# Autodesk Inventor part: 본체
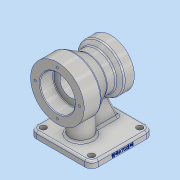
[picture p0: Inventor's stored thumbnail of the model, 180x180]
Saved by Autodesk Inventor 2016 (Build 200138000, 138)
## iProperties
Created: 2019-01
Part Number: 본체
Material: 알루미늄 6061
Document SubType Name: Modeling
Designer: 3sil_cad018
Density: 2.7 g/cm^3
Appearance: 알루미늄 - 평지
Author: 3sil_cad018
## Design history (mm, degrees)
sketch "스케치1"
  geometry: L1 (-51, 0)-(29, 0); L2 (-51, 0)-(-51, 40); L3 (-51, 40)-(-26, 40); L4 (-26, 40)-(-5.215, 28); L5 (-5.215, 28)-(8.126, 28); L6 (8.126, 28)-(14, 35); L7 (14, 35)-(29, 35); L8 (29, 35)-(29, 0); 2 further points
  constraints: 16 end point, 2 parallel, 2 vertical, 1 horizontal, 1 midpoint, 1 perpendicular, 1 point on line
  dimensions: "d0" = 80 distance of L1.start L1.end; "d1" = 80 diameter of L3 L1; "d2" = 25 distance of L2.end L3.end; "d3" = 15 distance of L6.end L7.end; "d4" = 70 diameter of L7 L1; "d5" = 30 deg angle of L4 L5; "d6" = 50 deg angle of L6 L5; "d7" = 51 distance from line of point (0, 0) L2; "d8" = 56 diameter of L5 L1
revolve "회전1" sketch "스케치1" stored, may be unused: angle "d9" = 90 deg
node "작업 평면1"
sketch "스케치2"
  geometry: L1 (46, 46)-(-46, 46); L2 (-46, 46)-(-46, -46); L3 (-46, -46)-(46, -46); L4 (46, -46)-(46, 46); L5 (46, 46)-(-46, -46); L6 (-46, 46)-(46, -46); 1 further point
  constraints: 12 end point, 2 midpoint, 2 parallel, 1 horizontal, 1 perpendicular
  dimensions: "d11" = 92 distance of L3.end L2.end; "d12" = 92 distance of L2.end L1.end
extrude "돌출1" join sketch "스케치2" distance "d13" = 10; taper "d14" = 0 deg
sketch "스케치3"
  geometry: L1 (-70.4, 0)-(65.4, 0) reference; L2 (-46, 46)-(-46, -46) reference; C1 r 16 at (-16, 0); 1 further point
  constraints: 1 centre point, 1 point on line
  dimensions: "d15" = 32 diameter of C1; "d16" = 30 distance from line of C1.centre L2
extrude "돌출2" join sketch "스케치3" stored distance "d17" = 10; taper "d18" = 0 deg
sketch "스케치4"
  geometry: L1 (0, -70)-(0, -28) reference; L2 (46, -70)-(-46, -70) reference; L3 (14, -35)-(29, -35) reference; L4 (36, -70)-(19.679, -35); L5 (46, -80)-(46, -70) reference; 1 further point
  constraints: 2 end point, 2 point on line
  dimensions: "d19" = 10 distance from line of L5 L4.start; "d20" = 25 deg angle of L4 L5
feature "리브1" sketch "스케치4" dims "d21" = 1, "d22" = 10, "d23" = 0, "d24" = 0, "d25" = 1, "d26" = 1
fillet "모깎기1" dims "d27" = 10
hole "구멍1" diameter "d30" = 9; stored, may be unused: countersink angle "d34" = 90 deg, drill point angle "d36" = 118 deg; dims "d28" = 10, "d29" = 10, "d31" = 6, "d32" = 4, "d33" = 2, "d35" = 8
hole "구멍2" diameter "d39" = 9; stored, may be unused: countersink angle "d43" = 90 deg, drill point angle "d45" = 118 deg; dims "d37" = 10, "d38" = 10, "d40" = 6, "d41" = 4, "d42" = 2, "d44" = 8
hole "구멍3" diameter "d48" = 9; stored, may be unused: countersink angle "d52" = 90 deg, drill point angle "d54" = 118 deg; dims "d46" = 10, "d47" = 10, "d49" = 6, "d50" = 4, "d51" = 2, "d53" = 8
hole "구멍4" diameter "d57" = 9; stored, may be unused: countersink angle "d61" = 90 deg, drill point angle "d63" = 118 deg; dims "d55" = 10, "d56" = 10, "d58" = 6, "d59" = 4, "d60" = 2, "d62" = 8
sketch "스케치5"
  geometry: C1 r 26 at (0, 0); 1 further point
  constraints: 1 centre point, 1 coincident
  dimensions: "d64" = 52 diameter of C1
extrude "돌출3" cut sketch "스케치5" distance "d65" = 20; taper "d66" = 0 deg
sketch "스케치6"
  geometry: C1 r 20 at (0, 0); 1 further point
  constraints: 1 centre point, 1 coincident
  dimensions: "d67" = 40 diameter of C1
extrude "돌출4" cut sketch "스케치6" distance "d68" = 17; taper "d69" = 0 deg
sketch "스케치7"
  geometry: C1 r 16 at (0, 0); 1 further point
  constraints: 1 centre point, 1 coincident
  dimensions: "d70" = 32 diameter of C1
extrude "돌출5" cut sketch "스케치7" stored distance "d71" = 17; taper "d72" = 0 deg
fillet "모깎기2" dims "d73" = 0.6
fillet "모깎기3" dims "d74" = 1
sketch "스케치8" dims "d75" = 66
  geometry: 3 further points
  constraints: 2 vertical alignment, 1 coincident, 2 other
hole "구멍5" sketch "스케치8" at (0, 33) diameter "d76" = 3.242; stored, may be unused: countersink angle "d80" = 90 deg, drill point angle "d82" = 118 deg; dims "d77" = 9, "d78" = 4, "d79" = 2, "d81" = 11
sketch "스케치9" dims "d86" = 55
  geometry: C1 r 25 at (0, 0) reference; 3 further points
  constraints: 2 vertical alignment, 1 coincident, 2 other
hole "구멍6" sketch "스케치9" at (0, -27.5) diameter "d87" = 3.242; stored, may be unused: countersink angle "d91" = 90 deg, drill point angle "d93" = 118 deg; dims "d88" = 9, "d89" = 4, "d90" = 2, "d92" = 11
sketch "스케치10"
  geometry: L1 (-10, 10)-(-10, 0) reference; L2 (82, 0)-(72, 0) reference; 2 further points
  constraints: 1 other
  dimensions: "d97" = 46 distance from line of L1 point (36, 4); "d98" = 4 distance from line of L2 point (36, 4)
feature "엠보싱1" sketch "스케치10" dims "d99" = 0.5, "d100" = 0
fillet "모깎기4" dims "d101" = 3
fillet "모깎기5" dims "d102" = 3
fillet "모깎기6" dims "d103" = 3
fillet "모깎기7" dims "d104" = 3
chamfer "모따기1" distance "d105" = 1; stored, may be unused: second distance "d106" = 2, angle "d107" = 45 deg
node "솔리드1"
pattern_circular "원형 패턴1" dims angle "d84" = 360 deg
pattern_circular "원형 패턴2" dims angle "d95" = 360 deg
